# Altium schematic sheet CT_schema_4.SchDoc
size 611 x 325 mm
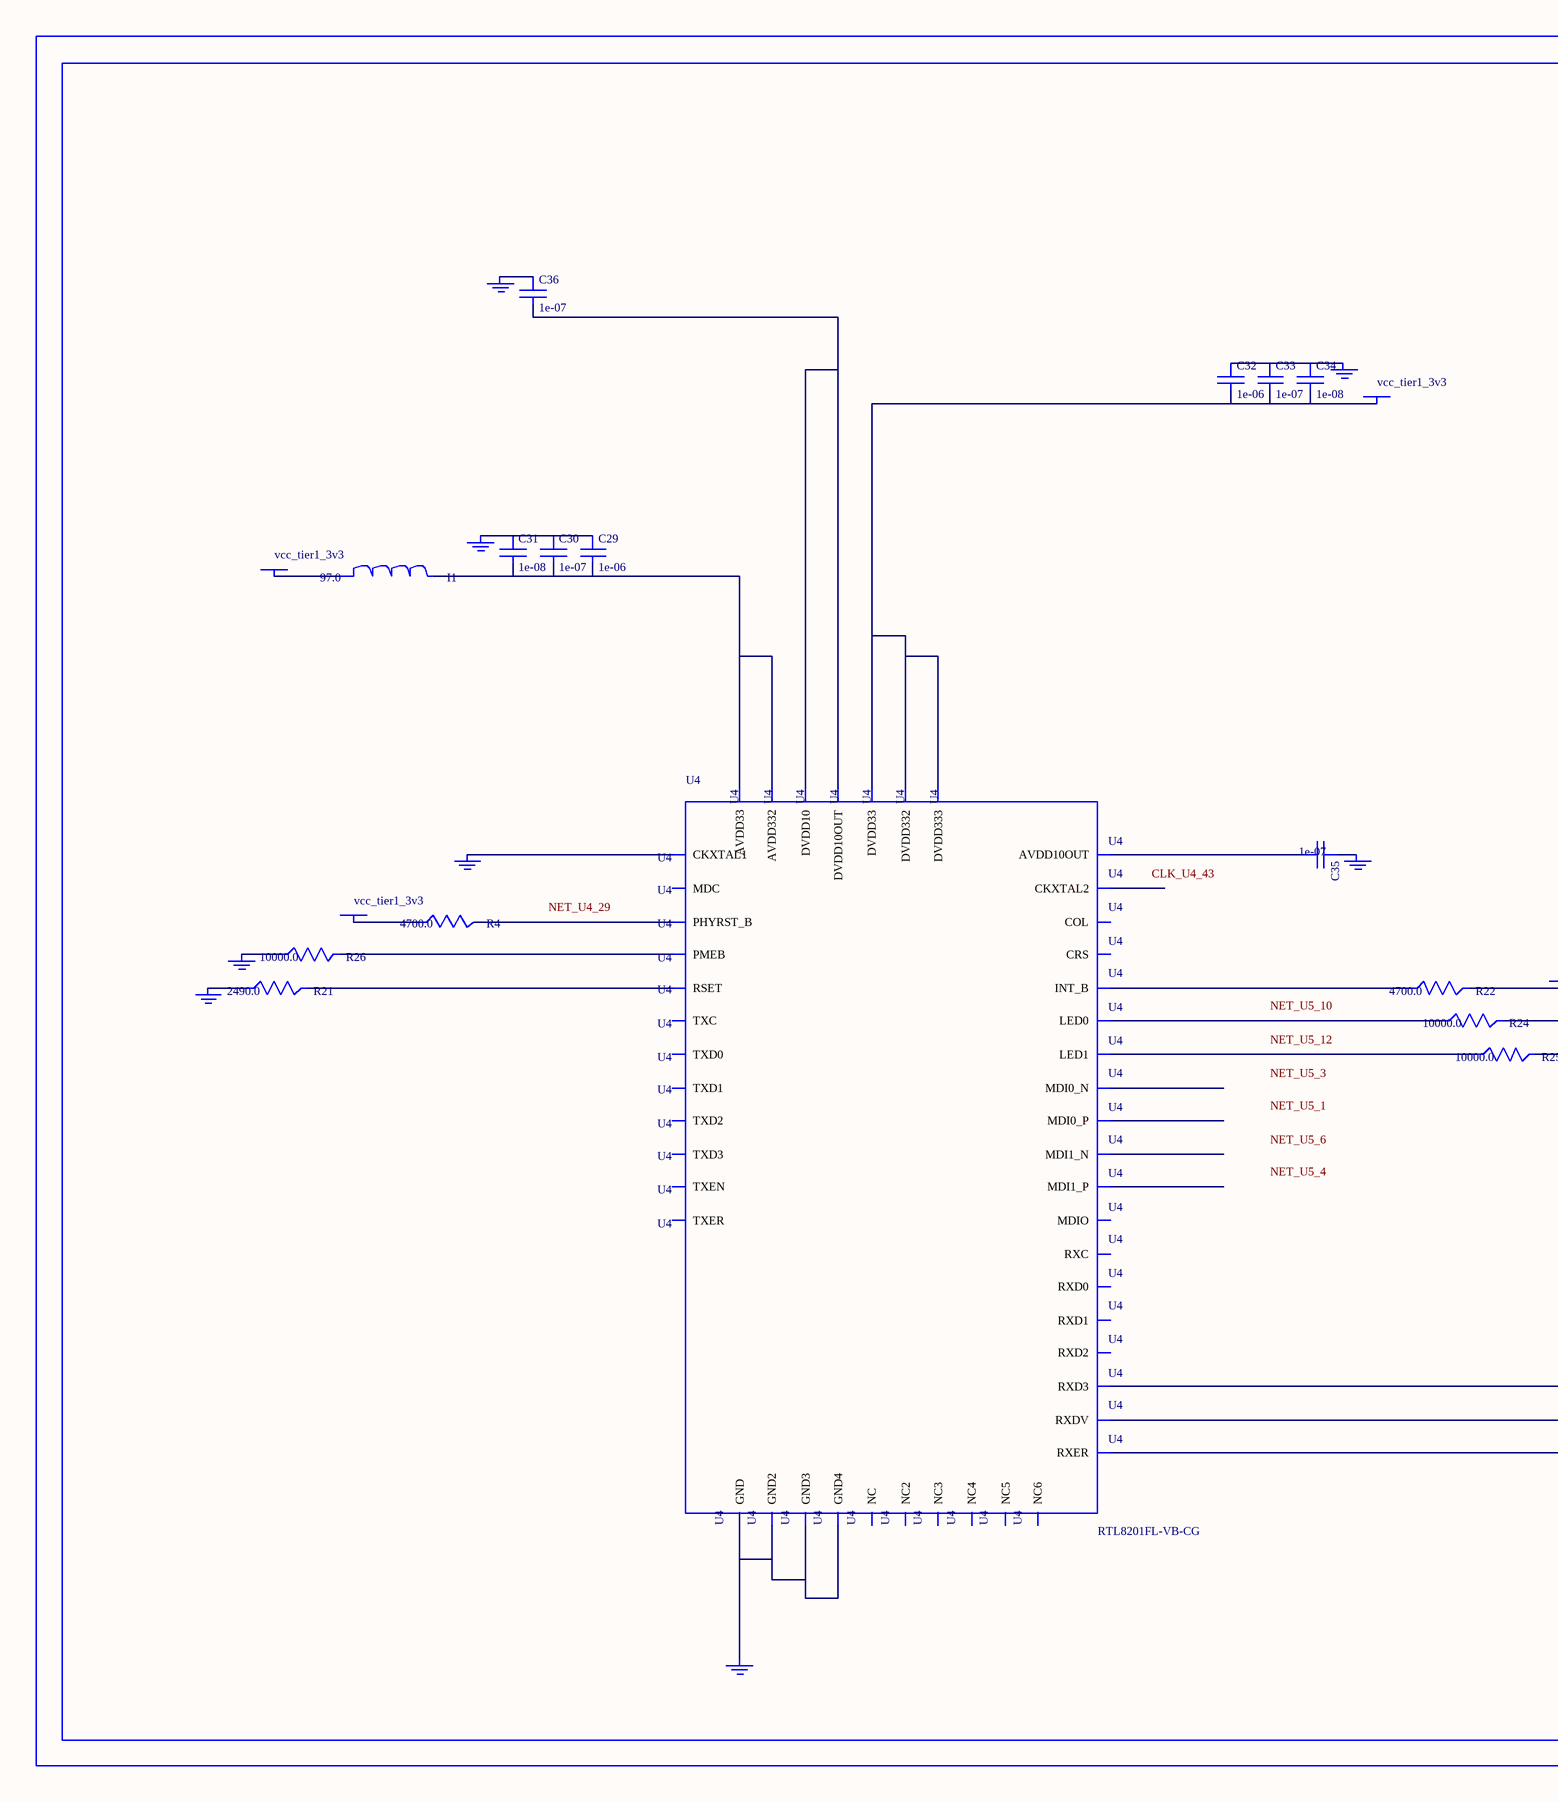
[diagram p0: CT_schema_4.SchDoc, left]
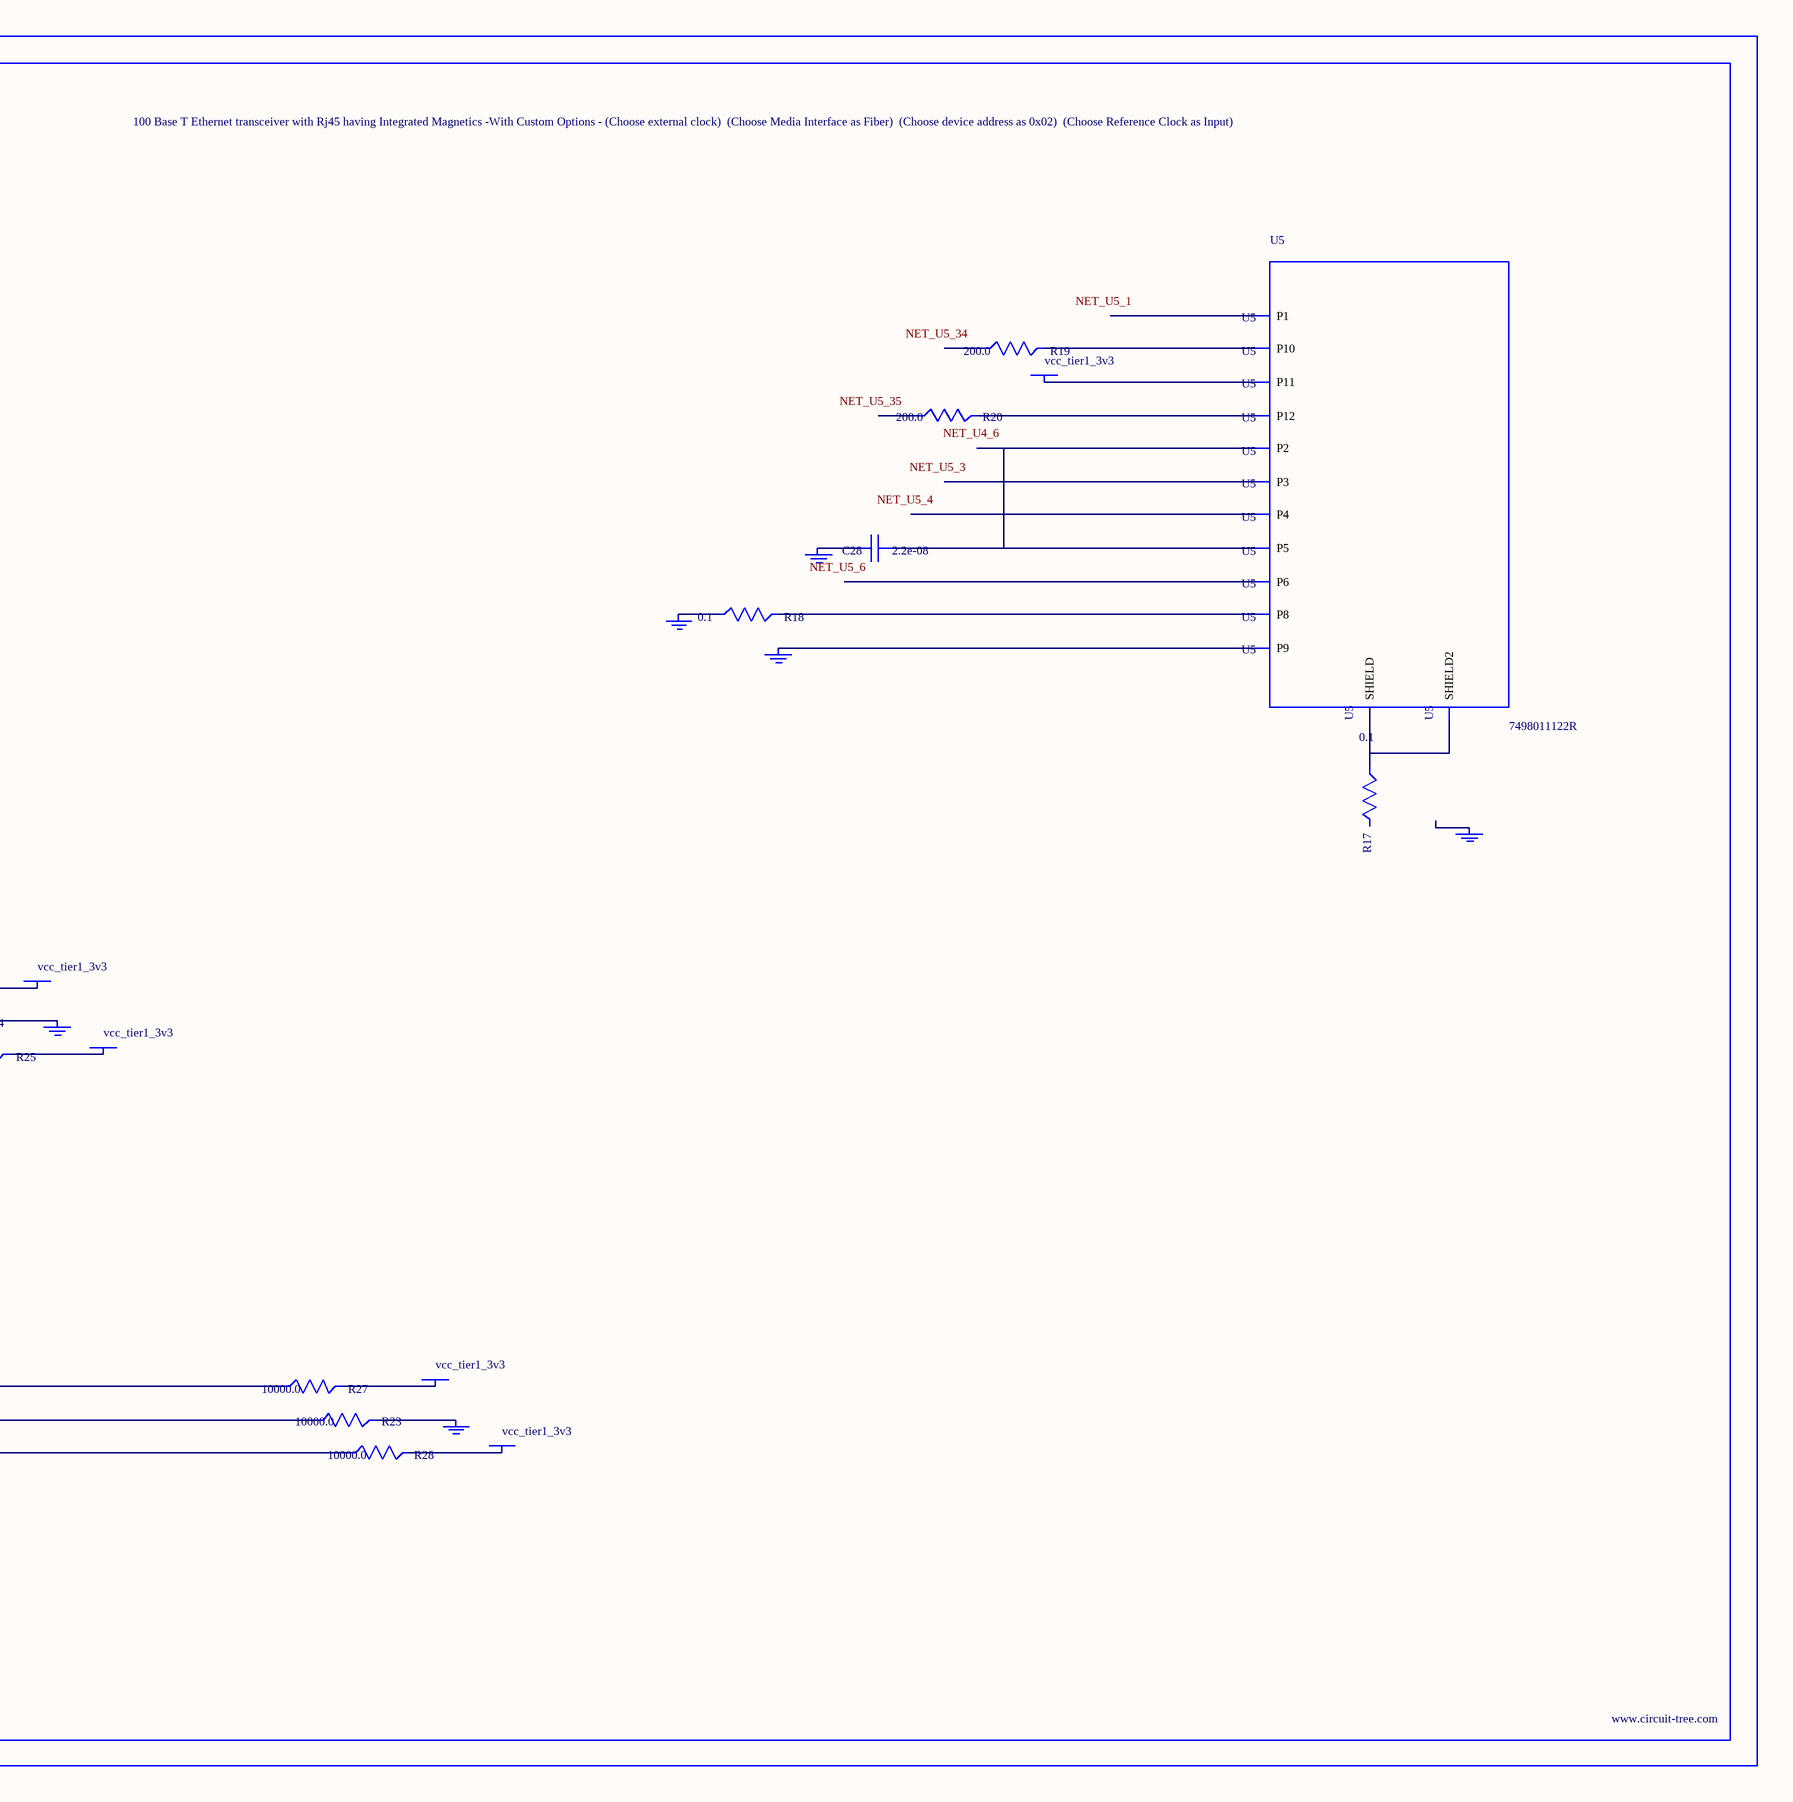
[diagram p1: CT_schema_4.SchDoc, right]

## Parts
BORDER3  (no value)
C28  2.2e-08  [C0402]
C29  1e-06  [C0603]
C30  1e-07  [C0402]
C31  1e-08  [C0402]
C32  1e-06  [C0603]
C33  1e-07  [C0402]
C34  1e-08  [C0402]
C35  1e-07  [C0402]
C36  1e-07  [C0402]
GND_INSTANCE_3_0  (no value)
GND_INSTANCE_3_1  (no value)
GND_INSTANCE_3_2  (no value)
GND_INSTANCE_3_3  (no value)
GND_INSTANCE_3_4  (no value)
GND_INSTANCE_3_5  (no value)
GND_INSTANCE_3_6  (no value)
GND_INSTANCE_3_7  (no value)
GND_INSTANCE_3_8  (no value)
GND_INSTANCE_3_9  (no value)
GND_INSTANCE_3_10  (no value)
GND_INSTANCE_3_11  (no value)
GND_INSTANCE_3_12  (no value)
GND_INSTANCE_3_13  (no value)
I1  97.0  [R0603]
POWER_INSTANCE_3_0  vcc_tier1_3v3
POWER_INSTANCE_3_1  vcc_tier1_3v3
POWER_INSTANCE_3_2  vcc_tier1_3v3
POWER_INSTANCE_3_3  vcc_tier1_3v3
POWER_INSTANCE_3_4  vcc_tier1_3v3
POWER_INSTANCE_3_5  vcc_tier1_3v3
POWER_INSTANCE_3_6  vcc_tier1_3v3
POWER_INSTANCE_3_7  vcc_tier1_3v3
R4  4700.0  [R0603]
R17  0.1  [R0603]
R18  0.1  [R0603]
R19  200.0  [R0603]
R20  200.0  [R0603]
R21  2490.0  [R0603]
R22  4700.0  [R0603]
R23  10000.0  [R0603]
R24  10000.0  [R0603]
R25  10000.0  [R0603]
R26  10000.0  [R0603]
R27  10000.0  [R0603]
R28  10000.0  [R0603]
U4  RTL8201FL-VB-CG  [RTL8201FL-VB-CG]
U5  7498011122R  [7498011122R]

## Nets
NetC28_1: C28.1 U5.2(P2) U5.5(P5)
NetC28_2: C28.2 GND_INSTANCE_3_10.0(GND)
NetC29_1: C29.1 C30.1 C31.1 GND_INSTANCE_3_0.0(GND)
NetC29_2: C29.2 C30.2 C31.2 I1.2 U4.6(AVDD33) U4.41(AVDD332)
NetC32_1: C32.1 C33.1 C34.1 GND_INSTANCE_3_3.0(GND)
NetC32_2: C32.2 C33.2 C34.2 POWER_INSTANCE_3_1.0(PWR) U4.15(DVDD33) U4.21(DVDD332) U4.37(DVDD333)
NetC35_1: C35.1 GND_INSTANCE_3_8.0(GND)
NetC35_2: C35.2 U4.48(AVDD10OUT)
NetC36_1: C36.1 GND_INSTANCE_3_5.0(GND)
NetC36_2: C36.2 U4.28(DVDD10) U4.40(DVDD10OUT)
NetGND_INSTANCE_3_1_0: GND_INSTANCE_3_1.0(GND) R26.1
NetGND_INSTANCE_3_2_0: GND_INSTANCE_3_2.0(GND) R23.2
NetGND_INSTANCE_3_4_0: GND_INSTANCE_3_4.0(GND) R24.2
NetGND_INSTANCE_3_6_0: GND_INSTANCE_3_6.0(GND) U4.42(CKXTAL1)
NetGND_INSTANCE_3_7_0: GND_INSTANCE_3_7.0(GND) R21.1
NetGND_INSTANCE_3_9_0: GND_INSTANCE_3_9.0(GND) U4.7(GND) U4.20(GND2) U4.33(GND3) U4.47(GND4)
NetGND_INSTANCE_3_11_0: GND_INSTANCE_3_11.0(GND) R18.1
NetGND_INSTANCE_3_12_0: GND_INSTANCE_3_12.0(GND) U5.9(P9)
NetI1_1: I1.1 POWER_INSTANCE_3_0.0(PWR)
NetPOWER_INSTANCE_3_2_0: POWER_INSTANCE_3_2.0(PWR) R27.2
NetPOWER_INSTANCE_3_3_0: POWER_INSTANCE_3_3.0(PWR) R22.2
NetPOWER_INSTANCE_3_4_0: POWER_INSTANCE_3_4.0(PWR) R25.2
NetPOWER_INSTANCE_3_5_0: POWER_INSTANCE_3_5.0(PWR) R28.2
NetPOWER_INSTANCE_3_6_0: POWER_INSTANCE_3_6.0(PWR) R4.1
NetPOWER_INSTANCE_3_7_0: POWER_INSTANCE_3_7.0(PWR) U5.11(P11)
NetR4_2: R4.2 U4.29(PHYRST_B)
NetR17_1: R17.1 U5.13(SHIELD) U5.14(SHIELD2)
NetR18_2: R18.2 U5.8(P8)
NetR19_2: R19.2 U5.10(P10)
NetR20_2: R20.2 U5.12(P12)
NetR21_2: R21.2 U4.46(RSET)
NetR22_1: R22.1 U4.32(INT_B)
NetR23_1: R23.1 U4.13(RXDV)
NetR24_1: R24.1 U4.34(LED0)
NetR25_1: R25.1 U4.35(LED1)
NetR26_2: R26.2 U4.10(PMEB)
NetR27_1: R27.1 U4.18(RXD3)
NetR28_1: R28.1 U4.39(RXER)

Not connected (* = marked no-connect by the designer): GND_INSTANCE_3_13 0(GND); R17 2; R19 1; R20 1; U4 1(MDI0_P) 2(MDI0_N) 3(NC) 4(MDI1_P) 5(MDI1_N) 8(NC2) 9(NC3) 11(NC4) 12(TXER) 14(RXD0) 16(RXD1) 17(RXD2) 19(RXC) 22(TXC) 23(TXD0) 24(TXD1) 25(TXD2) 26(TXD3) 27(TXEN) 30(MDC) 31(MDIO) 36(CRS) 38(COL) 43(CKXTAL2) 44(NC5) 45(NC6); U5 1(P1) 3(P3) 4(P4) 6(P6)

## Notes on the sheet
- Labels drawn without touching a wire or pin: CLK_U4_43, NET_U4_6, NET_U4_29, NET_U5_1, NET_U5_3, NET_U5_4, NET_U5_6, NET_U5_10, NET_U5_12, NET_U5_34, NET_U5_35

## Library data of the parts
BORDER3 = BORDER_PAGE3
C28 = C0402C223K3RAC
C29 C32 = C0603C105K3RACTU
C30 C33 C35 C36 = C0402C104K3RACTU
C31 C34 = C0402C103K3RAC
GND_INSTANCE_3_0-GND_INSTANCE_3_13 = GND
I1 = I1
POWER_INSTANCE_3_0-POWER_INSTANCE_3_7 = PWR
R4 R22 = RC0603JR-074K7L
R17 R18 = ERJ-3RSFR10V
R19 R20 = RC0603JR-07200RL
R21 = ERA-3AED2490V
R23-R28 = RC0603JR-0710KL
